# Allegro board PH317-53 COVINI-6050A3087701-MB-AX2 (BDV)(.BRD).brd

Outline 318.81 x 181 mm; copper layers: TOP, L2, L3, L4, L5, L6, L7, L8, L9, L10, L11, BOTTOM. Coordinates in mm from the lower left corner of the outline.

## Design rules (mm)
net group 1V8_MAIN_R_EN: nets 1V8_MAIN_R_EN GPIO4_1V8_MAIN_EN
net group 1V8S_DGPU_PG: nets 1V8_AON_PG 1V8S_DGPU_PG
net group ADC_MUX_R_SEL: nets ADC_MUX_R_SEL GPIO28_ADC_MUX_SEL
net group ALL_POWER_GOOD: nets ALL_POWER_GOOD DGPU_PWROK
net group ALL_PWGD_IN: nets ALL_PWGD_IN EN_PVCORE
net group ALL_PWGD_INTO_EC: nets ALL_PWGD_INTO_EC VCCIO_PG
net group AUD_CPU_SCLK: nets AUD_CPU_SCLK AUD_CPU_SCLK_R
net group AUD_CPU_SDI: nets AUD_CPU_SDI AUD_PCH_SDO
net group AUD_CPU_SDOP: nets AUD_CPU_SDOP AUD_PCH_SDI
net group BATT_CLK: nets BATT_CLK EC_SMB1_CLK
net group CHARGE_USBPWR_EN: nets CHARGE_USBPWR_EN USB_PWR_EN
net group CLINKCLK: nets CL_CLK1 CLINKCLK
net group CLINKDAT: nets CL_DATA1 CLINKDAT
net group CLINKRST#: nets CL_RST#1 CLINKRST#
net group CLK_CPU_D: nets CLK_CPU_DN CLK_CPU_DP
net group CLK_CPU_PCIBCLK_D: nets CLK_CPU_PCIBCLK_DN CLK_CPU_PCIBCLK_DP
net group CLK_CPUNSSC_D: nets CLK_CPUNSSC_DN CLK_CPUNSSC_DP
net group CLK_LAN_D: nets CLK_LAN_DN CLK_LAN_DP
net group CLK_PCIE_DGPU_100MHZ_: nets CLK_PCIE_DGPU_100MHZ_N CLK_PCIE_DGPU_100MHZ_P
net group CLK_PCIE_SSD1_D: nets CLK_PCIE_SSD1_DN CLK_PCIE_SSD1_DP
net group CLK_PCIE_SSD2_D: nets CLK_PCIE_SSD2_DN CLK_PCIE_SSD2_DP
net group CLK_WLAN_D: nets CLK_WLAN_DN CLK_WLAN_DP
net group CLKIN_XTAL: nets CLKIN_XTAL WLAN_CLK
net group CNV_BRI_DT: nets CNV_BRI_DT CNV_BRI_DT_R
net group CNV_BRI_RSP: nets CNV_BRI_RSP CNV_BRI_RSP_R
net group CNV_PA_BLANKING: nets CNV_PA_BLANKING CNV_PA_BLANKING_R
net group CNV_RF_RESET#_R: nets CNV_RF_RESET# CNV_RF_RESET#_R
net group CNV_RGI_DT: nets CNV_RGI_DT CNV_RGI_DT_R
net group CNV_RGI_RSP: nets CNV_RGI_RSP CNV_RGI_RSP_R
net group CNV_UART_RXD: nets CNV_UART_RXD CNV_UART_RXD_R
net group CNV_UART_TXD: nets CNV_UART_TXD CNV_UART_TXD_R
net group CPU2PCH_TRIGGER: nets CPU2PCH_TRIGGER CPU_TRIGOUT
net group DB_CLK_LAN_D: nets DB_CLK_LAN_DN DB_CLK_LAN_DP
net group DB_LAN_CLKREQ13#: nets DB_CLKREQ13_LAN# DB_LAN_CLKREQ13#
net group DB_PCIE_LAN_RX13: nets DB_PCIE_LAN_RX13N DB_PCIE_LAN_RX13P
net group DB_SPK_OUT_R_L_N: nets DB_SPK_OUT_R_L_N DB_SPK_OUT_R_L_P
net group DB_SPK_OUT_R_R_N: nets DB_SPK_OUT_R_R_N DB_SPK_OUT_R_R_P
net group DB_WOL_PWEN: nets DB_WOL_PWEN Q4021
net group DDR4_DRAMRST#_CPU: nets DDR4_DRAMRST#_CPU UNNAMED_284_CSC0402_I129_A
net group DDR_CA_CPU_VREF_RC: nets DDR_CA_CPU_VREF_A DDR_CA_CPU_VREF_RC
net group DDR_DQ_CPU_VREF_RC: nets DDR_DQ_CPU_VREF_B DDR_DQ_CPU_VREF_RC
net group DDR_PG_CTRL: nets DDR_PG_CTRL DDR_PG_CTRL_R
net group DDR_VTT_PG_CTRL: nets DDR_VTT_PG_CTRL EN_VTT
net group DGPU_ROM_CS#: nets DGPU_ROM_CS# VBIOS_CS#
net group DGPU_ROM_SCLK: nets DGPU_ROM_SCLK VBIOS_SCLK
net group DGPU_ROM_SI: nets DGPU_ROM_SI VBIOS_SI
net group DGPU_XTAL_OUT_DP: nets DGPU_XTAL_IN DGPU_XTAL_OUT
net group DMI_RX0_D: nets DMI_RX0_DN DMI_RX0_DP
net group DMI_RX1_D: nets DMI_RX1_DN DMI_RX1_DP
net group DMI_RX2_D: nets DMI_RX2_DN DMI_RX2_DP
net group DMI_RX3_D: nets DMI_RX3_DN DMI_RX3_DP
net group DMI_TX0_D: nets DMI_TX0_DN DMI_TX0_DP
net group DMI_TX1_D: nets DMI_TX1_DN DMI_TX1_DP
net group DMI_TX2_D: nets DMI_TX2_DN DMI_TX2_DP
net group DMI_TX3_D: nets DMI_TX3_DN DMI_TX3_DP
net group DMIC_DATA: nets DMIC__R_DATA DMIC_DATA
net group DP_CABLE_DET: nets DP_CABLE_DET DP_CABLE_R_DET
net group DP_IFPB_AUX: nets DP_IFPB_AUX DP_IFPB_AUX#
net group EC_CTL1: nets CTL1 EC_CTL1
net group EC_CTL2: nets CTL2 EC_CTL2
net group EC_CTL3: nets CTL3 EC_CTL3
net group EC_SMB1_DATA: nets EC_SMB1_DATA UNNAMED_131_CN082G_I95_3
net group EDP_PWM: nets EDP_PWM INV_PWM_PCH
net group EN_1V8: nets EN_1V8 UNNAMED_266_RSC0402_I167_A
net group EVENT_PCH#: nets EVENT_PCH# GPU_EVENT_PCH#
net group FBA_CLK0: nets FBA_CLK0 FBA_CLK0#
net group FBA_CLK1: nets FBA_CLK1 FBA_CLK1#
net group FBA_WCK01: nets FBA_WCK01 FBA_WCK01#
net group FBA_WCK23: nets FBA_WCK23 FBA_WCK23#
net group FBA_WCK45: nets FBA_WCK45 FBA_WCK45#
net group FBA_WCK67: nets FBA_WCK67 FBA_WCK67#
net group FBA_WCKB01: nets FBA_WCKB01 FBA_WCKB01#
net group FBA_WCKB23: nets FBA_WCKB23 FBA_WCKB23#
net group FBA_WCKB45: nets FBA_WCKB45 FBA_WCKB45#
net group FBA_WCKB67: nets FBA_WCKB67 FBA_WCKB67#
net group FBB_CLK0: nets FBB_CLK0 FBB_CLK0#
net group FBB_CLK1: nets FBB_CLK1 FBB_CLK1#
net group FBB_WCK01: nets FBB_WCK01 FBB_WCK01#
net group FBB_WCK23: nets FBB_WCK23 FBB_WCK23#
net group FBB_WCK45: nets FBB_WCK45 FBB_WCK45#
net group FBB_WCK67: nets FBB_WCK67 FBB_WCK67#
net group FBB_WCKB01: nets FBB_WCKB01 FBB_WCKB01#
net group FBB_WCKB23: nets FBB_WCKB23 FBB_WCKB23#
net group FBB_WCKB45: nets FBB_WCKB45 FBB_WCKB45#
net group FBB_WCKB67: nets FBB_WCKB67 FBB_WCKB67#
net group FBC_CLK0: nets FBC_CLK0 FBC_CLK0#
net group FBC_CLK1: nets FBC_CLK1 FBC_CLK1#
net group FBC_WCK01: nets FBC_WCK01 FBC_WCK01#
net group FBC_WCK23: nets FBC_WCK23 FBC_WCK23#
net group FBC_WCK45: nets FBC_WCK45 FBC_WCK45#
net group FBC_WCK67: nets FBC_WCK67 FBC_WCK67#
net group FBC_WCKB01: nets FBC_WCKB01 FBC_WCKB01#
net group FBC_WCKB23: nets FBC_WCKB23 FBC_WCKB23#
net group FBC_WCKB45: nets FBC_WCKB45 FBC_WCKB45#
net group FBC_WCKB67: nets FBC_WCKB67 FBC_WCKB67#
net group FBD_CLK0: nets FBD_CLK0 FBD_CLK0#
net group FBD_CLK1: nets FBD_CLK1 FBD_CLK1#
net group FBD_WCK01: nets FBD_WCK01 FBD_WCK01#
net group FBD_WCK23: nets FBD_WCK23 FBD_WCK23#
net group FBD_WCK45: nets FBD_WCK45 FBD_WCK45#
net group FBD_WCK67: nets FBD_WCK67 FBD_WCK67#
net group FBD_WCKB01: nets FBD_WCKB01 FBD_WCKB01#
net group FBD_WCKB23: nets FBD_WCKB23 FBD_WCKB23#
net group FBD_WCKB45: nets FBD_WCKB45 FBD_WCKB45#
net group FBD_WCKB67: nets FBD_WCKB67 FBD_WCKB67#
net group GC6_FB_EN_PCH: nets GC6_FB_EN_PCH GC6_FB_EN_PCH1
net group GPU_GND_SENSE: nets GPU_GND_SENSE NVVDD_GND_SENSE
net group GPU_HDMI_SCL: nets GPU_HDMI_SCL HDMI_GPU_SCL
net group GPU_HDMI_SDA: nets GPU_HDMI_SDA HDMI_GPU_SDA
net group GPU_NVVDD_SENSE: nets GPU_NVVDD_SENSE NVVDD_VCC_SENSE
net group GPU_OVERT_NVVDD#: nets 1V8_MAIN_EN_LEVEL GPU_OVERT_NVVDD#
net group GPU_PG: nets GPU_PG NVVDD_PG
net group GPU_THM_CLK: nets EC_SMBCLK0 GPU_THM_CLK
net group GPU_THM_DAT: nets EC_SMBDATA0 GPU_THM_DAT
net group H_PM_DOWN: nets H_PM_DOWN H_PM_DOWN_R
net group H_PM_SYNC: nets H_PM_SYNC H_PM_SYNC_R
net group H_PRDY#: nets H_PRDY# PCH_PRDY#
net group H_PREQ#: nets H_PREQ# PCH_PREQ#
net group H_TCK: nets H_TCK PCH_JTAGX
net group H_TDI: nets H_TDI PCH_TDI
net group H_TDO: nets H_TDO PCH_TDO
net group H_THERM#: nets H_THERM# THERMTRIP#
net group H_THERMDA: nets H_THERMDA H_THERMDC
net group H_TMS: nets H_TMS PCH_TMS
net group H_TRST#: nets H_TRST# PCH_TRST#
net group HDA_R_SDIN0: nets HDA_R_SDIN0 HDA_SDIN0
net group HDA_RST#: nets HDA_R_RST# HDA_RST#
net group HDA_SYNC: nets HDA_R_SYNC HDA_SYNC
net group HDMI_CN_DDCCLK: nets HDMI_CN_DDCCLK UNNAMED_171_NMOS2D2SDIODE_I12_2
net group HDMI_CN_DDCDATA: nets HDMI_CN_DDCDATA UNNAMED_171_NMOS2D2SDIODE_I12_4
net group HDMI_MPC_SCL: nets HDMI_MPC_SCL SMB0_CLK_D
net group HDMI_MPC_SDA: nets HDMI_MPC_SDA SMB0_DATA_D
net group HDMI_OUT_R_HPD: nets HDMI_CN_HPD HDMI_OUT_R_HPD
net group HDMI_RET_HPD: nets HDMI_NV_Q_HPD HDMI_RET_HPD
net group HPS: nets HPS UNNAMED_289_ALC255CG_I118_HP
net group I2CC_SCL_G: nets I2CC_SCL_G I2CC_SCL_R_G
net group I2CC_SDA_G: nets I2CC_SDA_G I2CC_SDA_R_G
net group I2CS_SCL_G: nets I2CS_SCL_G I2CS_SCL_R_G
net group I2CS_SDA_G: nets I2CS_SDA_G I2CS_SDA_R_G
net group I_ADP_R: nets HW_I_ADC I_ADP_R
net group IDCHG: nets IDCHG UNNAMED_264_IT8987ECX_I608_ADC1
net group IFPCD_PLLVDD: nets IFPCD_PLLVDD IFPE_PLLVDD
net group IRMT_HOLD_RST#: nets IRMT_HOLD_RST# PCH_HOLD_RST#
net group LAN_MDI3: nets LAN_MDI3N LAN_MDI3P
net group LAN_TRD0_CN_D: nets LAN_TRD0_CN_DN LAN_TRD0_CN_DP
net group LAN_TRD1_CN_D: nets LAN_TRD1_CN_DN LAN_TRD1_CN_DP
net group LAN_TRD2_CN_D: nets LAN_TRD2_CN_DN LAN_TRD2_CN_DP
net group LAN_TRD3_CN_D: nets LAN_TRD3_CN_DN LAN_TRD3_CN_DP
net group LCM_VDDEN: nets LCM_VDDEN UNNAMED_166_CSC0402_I36_A
net group LID_SW#_R: nets LID_SW# LID_SW#_R
net group LOW_PWR_VTG_SHIFT: nets LOW_PWR_VTG_SHIFT VID0_VCCIO
net group LOW_PWR_VTG_SHIFT_N: nets LOW_PWR_VTG_SHIFT_N VID1_VCCIO
net group LPC_AD<0>: nets LPC_AD<0> LPC_ESPI_IO0
net group LPC_AD<1>: nets LPC_AD<1> LPC_ESPI_IO1
net group LPC_AD<2>: nets LPC_AD<2> LPC_ESPI_IO2
net group LPC_AD<3>: nets LPC_AD<3> LPC_ESPI_IO3
net group M2_SSD1_DET#: nets M2_SSD1_DET# UNNAMED_160_NMOS_I89_G
net group M_A_DQS0_D: nets M_A_DQS0_DN M_A_DQS0_DP
net group M_A_DQS1_D: nets M_A_DQS1_DN M_A_DQS1_DP
net group M_A_DQS2_D: nets M_A_DQS2_DN M_A_DQS2_DP
net group M_A_DQS3_D: nets M_A_DQS3_DN M_A_DQS3_DP
net group M_A_DQS4_D: nets M_A_DQS4_DN M_A_DQS4_DP
net group M_A_DQS5_D: nets M_A_DQS5_DN M_A_DQS5_DP
net group M_A_DQS6_D: nets M_A_DQS6_DN M_A_DQS6_DP
net group M_A_DQS7_D: nets M_A_DQS7_DN M_A_DQS7_DP
net group M_B_DQS0_D: nets M_B_DQS0_DN M_B_DQS0_DP
net group M_B_DQS1_D: nets M_B_DQS1_DN M_B_DQS1_DP
net group M_B_DQS2_D: nets M_B_DQS2_DN M_B_DQS2_DP
net group M_B_DQS3_D: nets M_B_DQS3_DN M_B_DQS3_DP
net group M_B_DQS4_D: nets M_B_DQS4_DN M_B_DQS4_DP
net group M_B_DQS5_D: nets M_B_DQS5_DN M_B_DQS5_DP
net group M_B_DQS6_D: nets M_B_DQS6_DN M_B_DQS6_DP
net group M_B_DQS7_D: nets M_B_DQS7_DN M_B_DQS7_DP
net group M_CLK_DDR0_D: nets M_CLK_DDR0_DN M_CLK_DDR0_DP
net group M_CLK_DDR1_D: nets M_CLK_DDR1_DN M_CLK_DDR1_DP
net group M_CLK_DDR2_D: nets M_CLK_DDR2_DN M_CLK_DDR2_DP
net group M_CLK_DDR3_D: nets M_CLK_DDR3_DN M_CLK_DDR3_DP
net group MB_SHUTDOWN#: nets DGPU_PWRLEVEL MB_SHUTDOWN#
net group MODEM_CLKREQ_R: nets CNV_CLKREQ MODEM_CLKREQ_R
net group OVRM_EN_EC: nets OVRM_EN OVRM_EN_EC
net group PCH2CPU_TRIGGER: nets PCH2CPU_TRIGGER PCH_TRIGOUTGGER
net group PCH_I2C1_CLK: nets PCH_I2C1_CLK TP_I2C_CLK
net group PCH_I2C1_DATA: nets PCH_I2C1_DATA TP_I2C_DAT
net group PCH_SPI_SO2: nets PCH_SPI_SO2 UNNAMED_281_J44894_I301_SPI0IO2
net group PCH_SPI_SO3: nets PCH_SPI_SO3 UNNAMED_281_J44894_I301_SPI0IO3
net group PCH_THERMTRIP#: nets PCH_THERMTRIP# PCH_THERMTRIP#_R
net group PCH_VCCPRIM_1P8: nets PCH_VCCPRIM_1P8 PCH_VCCPRIM_1P8_R
net group PCIE_RCOMPN: nets PCIE_RCOMPN PCIE_RCOMPP
net group PCIE_SSD_RX9: nets PCIE_SSD_RX9N PCIE_SSD_RX9P
net group PCIE_SSD_RX10: nets PCIE_SSD_RX10N PCIE_SSD_RX10P
net group PCIE_SSD_RX11: nets PCIE_SSD_RX11N PCIE_SSD_RX11P
net group PCIE_SSD_RX12: nets PCIE_SSD_RX12N PCIE_SSD_RX12P
net group PCIE_SSD_RX21: nets PCIE_SSD_RX21N PCIE_SSD_RX21P
net group PCIE_SSD_RX22: nets PCIE_SSD_RX22N PCIE_SSD_RX22P
net group PCIE_SSD_RX23: nets PCIE_SSD_RX23N PCIE_SSD_RX23P
net group PCIE_SSD_RX24: nets PCIE_SSD_RX24N PCIE_SSD_RX24P
net group PCIE_WLAN_RX14: nets PCIE_WLAN_RX14N PCIE_WLAN_RX14P
net group PFM_PF_BSOK_RC: nets PFM_PF_BSOK_RC PFM_PF_R_BSOK
net group PVCORE_PG: nets PCH_PWROK PVCORE_PG
net group Q4001: nets Q4001 Q4023
net group REP_LAN_TX13: nets REP_LAN_TX13N REP_LAN_TX13P
net group SB_PWRBTN#_EC: nets SB_PWRBTN# SB_PWRBTN#_EC
net group SBPWR_EN_EC: nets SBPWR_EN_EC USBPWR_EN
net group SSD1_DEVSLP: nets DEVSLP_SSD1 SSD1_DEVSLP
net group SSD_CLKREQ2#: nets CLKREQ_SSD1# SSD_CLKREQ2#
net group SSD_CLKREQ3#: nets CLKREQ_SSD2# SSD_CLKREQ3#
net group THERM_SCI#: nets THERM_SCI# UNNAMED_262_RSC0402_I121_B
net group TPM_SPI_CS2#: nets PCH_SPI_CS2# TPM_SPI_CS2#
net group UNNAMED_131_CSC0603_I65_A: nets UNNAMED_131_CSC0603_I65_A UNNAMED_131_NMOSDUALC_I67_D1
net group UNNAMED_151_CSC0402_I5_A: nets UNNAMED_151_CSC0402_I5_A UNNAMED_151_NMOSC_I3_D
net group UNNAMED_153_1222UYOSUBCS530A4_1: nets UNNAMED_153_1222UYOSUBCS530A4_1 UNNAMED_153_NMOSDUALC_I22_D2
net group UNNAMED_153_1222UYOSUBCS530A4TR: nets UNNAMED_153_1222UYOSUBCS530A4TR UNNAMED_153_NMOSDUALC_I22_D1
net group UNNAMED_153_LEDSINGLE_I35_A1: nets UNNAMED_153_LEDSINGLE_I35_A1 UNNAMED_153_NMOSC_I26_D
net group UNNAMED_263_CSC0402_I83_A: nets UNNAMED_263_CSC0402_I83_A UNNAMED_263_NMOSC_I75_D
net group UNNAMED_285_J44894_I143_GPPA10: nets UNNAMED_285_J44894_I143_GPPA10 UNNAMED_285_RSC0402_I265_B
net group UNNAMED_289_ALC255CG_I118_CBN: nets UNNAMED_289_ALC255CG_I118_CBN UNNAMED_289_ALC255CG_I118_CBP
net group UNNAMED_314_CSC0402_I81_A: nets UNNAMED_314_CSC0402_I81_A UNNAMED_314_MP2886AGUZ_I21_VFB
net group USB2_REAR_3: nets USB2_REAR_3N USB2_REAR_3P
net group USB3_RX4: nets USB3_RX4N USB3_RX4P
net group USB3_RX5: nets USB3_RX5N USB3_RX5P
net group USB3_TX4: nets USB3_TX4N USB3_TX4P
net group USB3_TX5: nets USB3_TX5N USB3_TX5P
net group USB_P4_D: nets USB_P4_DN USB_P4_DP
net group USB_P5_D: nets USB_P5_DN USB_P5_DP
net group VCCGT_SENSE: nets VGT_VCCSENSE VGT_VSSSENSE
net group VCCIO_VSSSENSE: nets UNNAMED_139_CSC0402_I29_A VCCIO_VSSSENSE
net group VCCSA_SENSE: nets VCCSA_VCCSENSE VCCSA_VSSSENSE
net group VCCST_PWRGD: nets VCCST_PWRGD VCCST_PWRGD_CPU
net group VCORE_SENSE: nets VCCSENSE VSSSENSE
net group VR_SVID_ALERT#: nets VIDALERT# VR_SVID_ALERT#
net group VRACPU_SVID_CLK: nets VR_SVID_CLK VRACPU_SVID_CLK
net group VRACPU_SVID_DATA: nets VR_SVID_DATA VRACPU_SVID_DATA
net group VRB1V8S_BST: nets VRB1V8S_BST VRB1V8S_BST1
net group VSSMPHY_SENSE: nets VSSMPHY_SENSE VSSMPHY_SENSE_L
net group W4_S8: nets FAN1_PWM FAN2_PWM
net group WLAN_CLKREQ14#: nets CLKREQ14_WLAN# WLAN_CLKREQ14#
net group XTAL: nets DGPU_XTAL_OUTBUFF DGPU_XTAL_SSIN
net group 1V8_MAIN_EN_AND_LEVEL: nets 1V8_MAIN_EN_AND_LEVEL DGPU_PWR_EN DGPU_PWR_R_EN DIS_NVVDD EN_NVVDD EN_PEXVDD GPIO20_OR_FGC6 GPU_EN UNNAMED_169_NCT3521U_I119_3 UNNAMED_409_74LVC1G32_I108_1 UNNAMED_409_ANDGATE_I103_4
net group 19V_CURRENT_MONITOR_N: nets 19V_CURRENT_MONITOR_N 19V_CURRENT_MONITOR_P UNNAMED_402_CSC0402_I282_B UNNAMED_402_NCP45491XMNTWG_I2_4 UNNAMED_402_NCP45491XMNTWG_I2_6
net group ACDRV: nets UNNAMED_131_NMOSDUALC_I67_D2 UNNAMED_131_NMOSDUALC_I84_G2 VADPBL
net group ALWAYS_PW_EN: nets ALWAYS_PW_EN EN_3A5A EN_3V EN_5V EN_5V0 P5VDS_EN UNNAMED_132_RSC0402_I42_B UNNAMED_133_RSC0402_I17_B UNNAMED_134_CSC0402_I21_A UNNAMED_266_CSC0402_I474_A UNNAMED_266_NMOSC_I493_D
net group ASY: nets CATERR_N
net group AUDIO-B: nets DB_HP_R_L DB_HP_R_R RING2 SLEEVE
net group AVDDL: nets AVDDL AVDDVCO DVDDL
net group BATPRES#: nets BATPRES# BATT_IN# TS
net group BUF_PLT_RST#: nets BUF_PLT_RST# PCH_PLTRST#_BUF UNNAMED_264_IT8987ECX_I608_LPCR
net group CFG1_15: nets CFG<0> CFG<1> CFG<2> CFG<3> CFG<4> CFG<5> CFG<6> CFG<7> CFG<8> CFG<9> CFG<10> CFG<11> CFG<12> CFG<13> CFG<14> CFG<15>
net group CFG16_19: nets CFG<16> CFG<17> CFG<18> CFG<19>
net group CLK_LPC_EC: nets CLK_LPC_DEBUG_R CLK_LPC_EC LPC_ESPI_CLK UNNAMED_264_CSC0402_I634_A
net group CN_MIC: nets CN_MIC DB_MIC2_REF DB_RING2 DB_SLEEVE RING2_CONN
net group CORE_PWEN: nets CORE_PWEN CORE_PWEN_RC EN_VCCIO UNNAMED_265_APL3523A_I457_3 UNNAMED_265_APL3523A_I457_5 UNNAMED_265_APL3523A_I458_5 UNNAMED_315_NMOS_I101_G
net group CPU_C10_PWR_GATE#_R: nets CPU_C10_PWR_GATE#_R LP# UNNAMED_265_ANDGATE_I549_1
net group CPU_PROCHOT#: nets CPU_PROCHOT# CPU_PROCHOT#_R EC_CPU_PROCHOT# PROCHOT#
net group DB_PCIE_LAN_C_TX13N: nets UNNAMED_206_CSC0402_I359_A
net group DB_PCIE_LAN_C_TX13P: nets UNNAMED_206_CSC0402_I360_A
net group DIS_FBVDD: nets DIS_FBVDD EN_VRAM_DGPU FBVDD_EN_OR
net group DIS_PEXVDD: nets DIS_PEXVDD EN_1V0S_DGPU EN_PEXVDD_AND
net group DMIC_CLK: nets DMIC_CLK DMIC_CLK_R DMIC_R_CLK
net group DP_CLK: nets DPB_DDCCLK DPC_DDCCLK HDMI_DDCCLK HDMI_TXSCL
net group DP_CN_HPD: nets DP_CN_HPD DP_NA_HPD DP_NV_HPD DP_REP_HPD
net group DP_DATA: nets DPB_DDCDATA DPC_DDCDATA HDMI_TXSDA
net group EC_PECI: nets EC_PECI H_PECI PCH_PECI PCH_R_PECI
net group EC_PWRBTN#: nets EC_PWRBTN# UNNAMED_151_CN282G_I20_28 UNNAMED_264_IT8987ECX_I608_PWRS
net group EDP_BKLTEN: nets EDP_BKLTEN LCM_BKLTEN LID_SW_LCM#
net group ESPI_RST#: nets ESPI_RST# GPP_A7 KB_RST# SERIRQ SERIRQ_ESPI_RST# UNNAMED_285_RSC0402_I283_B
net group GND: nets AGND_AUDIO DGND_CHASSIS1 DGND_CHASSIS2 DGND_CHASSIS4 DGND_CHASSIS5 DGPU_FB_CAL_PU_GND DGPU_FB_CAL_TERM_GND GND_A GND_A1 GND_ALG GND_PB VRAM_DGPU_GND
net group GPU_DP_AUX: nets UNNAMED_398_CSC0402_I129_A
net group GPU_DP_AUX#: nets UNNAMED_398_CSC0402_I130_A
net group HDA_BCLK: nets HDA_BCLK HDA_R_BCLK HDA_R_BITCLK
net group HDA_SDO: nets HDA_SDO HDA_SDO_R ME_FLASH_EN
net group HDMI_ISP_SCL: nets HDMI_ISP_SCL HDMI_RET_SCL UNNAMED_171_NMOS2D2SDIODE_I12_3
net group HDMI_ISP_SDA: nets HDMI_ISP_SDA HDMI_RET_SDA UNNAMED_171_NMOS2D2SDIODE_I126_
net group HP_L: nets HP_L HP_R_L LINE1_L LINE1_REF_L
net group HP_R: nets HP_R HP_R_R LINE1_R LINE1_REF_R
net group I2C_RST#: nets I2C_RST# OVERT_RST# PEX_DGPU_RST#
net group LPC: nets ESPI_LPC#
net group M2_SSD1_SUSCLK: nets M2_SSD1_SUSCLK M2_SSD2_SUSCLK M2_WLAN_SUSCLK SUSCLK SUSCLK32_PCH
net group NVVDD_CURRENT_MONITOR_N: nets NVVDD_CURRENT_MONITOR_N NVVDD_CURRENT_MONITOR_P UNNAMED_402_CSC0402_I285_B UNNAMED_402_NCP45491XMNTWG_I2_1 UNNAMED_402_NCP45491XMNTWG_I2_5 UNNAMED_402_NCP45491XMNTWG_I2_7 UNNAMED_402_NCP45491XMNTWG_I267
net group NVVDD_PSI: nets GPIO6_NVVDD_PSI# NVVDD_PSI UNNAMED_314_MP2886AGUZ_I21_PSI
net group NVVDD_PWMID: nets GPIO0_GPU_VID NVVDD_PWMID UNNAMED_314_MP2886AGUZ_I21_PWMV
net group PCH_SPI_SO: nets PCH_SPI_SO SPI_EC_SO TPM_SPI_SO UNNAMED_281_J44894_I301_SPI0MIS
net group PCSPKR_EC_3: nets PCH_SPKR PCSPKR_EC_3 UNNAMED_289_ALC255CG_I118_PCBEE UNNAMED_289_CSC0402_I68_B
net group PEG_RCOMP: nets PEG_RCOMP
net group PFM_BG_REF_OUT: nets PFM_BG_REF_OUT PFM_BS_REF PFM_CM_REF_IN UNNAMED_402_NPND_I214_C
net group PWR: nets FBA1_VREFC FBA2_VREFC FBB1_VREFC FBB2_VREFC FBC1_VREFC FBC2_VREFC FBD1_VREFC FBD2_VREFC GPU_FB_VREF NV3V3_DPP_DIS P0V6S P0V6S_DIMM0_VREF_CA P0V6S_DIMM1_VREF_DQ P1V0S_DGPU P1V0S_HDMI P1V2 P1V05A P1V8_MAIN P1V8_MAIN_CT P1V8A P1V8A_1P P1V8S P1V8S_AON1 P1V8S_AON2 P1V8S_AUDIO P1V8S_MAIN1 P1V35S_FBVDDQ P2V5 P3V3_NV_SEQ P3V3_RTC P3V3A P3V3A_KBLED P3V3A_LAN P3V3A_PB P3V3A_WLAN P3V3AL P3V3AL_EC_AVCC P3V3AL_EC_FSPI P3V3AL_EC_VSTBY_PLL P3V3AL_RTC_BAT P3V3AL_RTC_BAT_BOT P3V3AL_RTC_BAT_R P3V3AL_SM P3V3DS P3V3DS_PB P3V3S P3V3S_DP P3V3S_DPP P3V3S_EC_VCC P3V3S_HDMI P3V3S_LCDVDD2 P3V3S_SENSOR P3V3S_TP P5V0 P5V0A_PB P5V0A_USB1 P5V0DS P5V0S P5V0S_AUDIO_AVDD P5V0S_FAN1 P5V0S_FAN2 P5V0S_HDMI P5V0S_KBLED P5V0S_PVDD PUSB3_PWR2 PVADPTR PVBAT PVBAT_CPU PVBAT_GT PVBAT_SA PVCCGT PVCCIO PVCCSA PVCCST PVCCSTG PVCORE PVCORE_DGPU PVPACK VCCPLL_OC VCCSFR VRAM_DGPU_VREF
net group REPEATER_HDMI_CLKN: nets UNNAMED_171_AZ104504FR7G_I86_5
net group REPEATER_HDMI_CLKP: nets UNNAMED_171_AZ104504FR7G_I86_4
net group REPEATER_HDMI_D0N: nets REPEATER_HDMI_D0N
net group REPEATER_HDMI_D0P: nets REPEATER_HDMI_D0P
net group REPEATER_HDMI_D1N: nets REPEATER_HDMI_D1N
net group REPEATER_HDMI_D1P: nets REPEATER_HDMI_D1P
net group REPEATER_HDMI_D2N: nets REPEATER_HDMI_D2N
net group REPEATER_HDMI_D2P: nets REPEATER_HDMI_D2P
net group RESUME_PWEN: nets 2V5_PG EN_2V5 EN_VDDQ PVCCSTG_EN RESUME_PWEN UNNAMED_265_ANDGATE_I549_4 UNNAMED_266_RSC0402_I529_A VCCPLL_OC_EN
net group RSMRST_EC: nets 3V3DS_PG RSMRST# RSMRST_EC UNNAMED_264_IT8987ECX_I608_LPCP UNNAMED_266_RSC0402_I374_A
net group SCAN_IN: nets SCAN_IN<0> SCAN_IN<1> SCAN_IN<2> SCAN_IN<3> SCAN_IN<4> SCAN_IN<5> SCAN_IN<6> SCAN_IN<7>
net group SCAN_OUT: nets SCAN_OUT<0> SCAN_OUT<1> SCAN_OUT<2> SCAN_OUT<3> SCAN_OUT<4> SCAN_OUT<5> SCAN_OUT<6> SCAN_OUT<7> SCAN_OUT<8> SCAN_OUT<9> SCAN_OUT<10> SCAN_OUT<11> SCAN_OUT<12> SCAN_OUT<13> SCAN_OUT<14> SCAN_OUT<15> SCAN_OUT<16> SCAN_OUT<17>
net group SCLK: nets I2C_CLK_LED I2CB_SCL_G I2CC_SCL PCH_3A_SMCLK PCH_3S_SMCLK PCH_I2C_CLK PCH_TCK SMB0_CLK TP_CLK WLAN_I2C_CLK XCLK_BIASREF
net group SCLK_DATA: nets DGPU_ROM_SO HDMI_DDCDATA I2C_DATA_LED I2CB_SDA_G I2CC_SDA PCH_3A_SMDATA PCH_3S_SMDATA PCH_I2C_DATA SMB0_DATA SMBALERT# TP_DATA WLAN_I2C_DAT
net group SDDR_A_ALERT: nets M_A_ALERT#
net group SDDR_A_CMD: nets M_A_A_0 M_A_A_1 M_A_A_2 M_A_A_3 M_A_A_4 M_A_A_5 M_A_A_6 M_A_A_7 M_A_A_8 M_A_A_9 M_A_A_10 M_A_A_11 M_A_A_12 M_A_A_13 M_A_ACT# M_A_BG0 M_A_BG1 M_A_BS0 M_A_BS1 M_A_CAS# M_A_PARITY M_A_RAS# M_A_WE# M_CKE0 M_CKE1 M_CS#0 M_CS#1 M_ODT0 M_ODT1
net group SDDR_A_DQ_BYTE0: nets M_A_DQ<0> M_A_DQ<1> M_A_DQ<2> M_A_DQ<3> M_A_DQ<4> M_A_DQ<5> M_A_DQ<6> M_A_DQ<7>
net group SDDR_A_DQ_BYTE1: nets M_A_DQ<8> M_A_DQ<9> M_A_DQ<10> M_A_DQ<11> M_A_DQ<12> M_A_DQ<13> M_A_DQ<14> M_A_DQ<15>
net group SDDR_A_DQ_BYTE2: nets M_A_DQ<16> M_A_DQ<17> M_A_DQ<18> M_A_DQ<19> M_A_DQ<20> M_A_DQ<21> M_A_DQ<22> M_A_DQ<23>
net group SDDR_A_DQ_BYTE3: nets M_A_DQ<24> M_A_DQ<25> M_A_DQ<26> M_A_DQ<27> M_A_DQ<28> M_A_DQ<29> M_A_DQ<30> M_A_DQ<31>
net group SDDR_A_DQ_BYTE4: nets M_A_DQ<32> M_A_DQ<33> M_A_DQ<34> M_A_DQ<35> M_A_DQ<36> M_A_DQ<37> M_A_DQ<38> M_A_DQ<39>
net group SDDR_A_DQ_BYTE5: nets M_A_DQ<40> M_A_DQ<41> M_A_DQ<42> M_A_DQ<43> M_A_DQ<44> M_A_DQ<45> M_A_DQ<46> M_A_DQ<47>
net group SDDR_A_DQ_BYTE6: nets M_A_DQ<48> M_A_DQ<49> M_A_DQ<50> M_A_DQ<51> M_A_DQ<52> M_A_DQ<53> M_A_DQ<54> M_A_DQ<55>
net group SDDR_A_DQ_BYTE7: nets M_A_DQ<56> M_A_DQ<57> M_A_DQ<58> M_A_DQ<59> M_A_DQ<60> M_A_DQ<61> M_A_DQ<62> M_A_DQ<63>
net group SDDR_B_ALERT: nets M_B_ALERT#
net group SDDR_B_CMD: nets M_B_A_0 M_B_A_1 M_B_A_2 M_B_A_3 M_B_A_4 M_B_A_5 M_B_A_6 M_B_A_7 M_B_A_8 M_B_A_9 M_B_A_10 M_B_A_11 M_B_A_12 M_B_A_13 M_B_ACT# M_B_BG0 M_B_BG1 M_B_BS0 M_B_BS1 M_B_CAS# M_B_PARITY M_B_RAS# M_B_WE# M_CKE2 M_CKE3 M_CS#2 M_CS#3 M_ODT2 M_ODT3
net group SDDR_B_DQ_BYTE0: nets M_B_DQ<0> M_B_DQ<1> M_B_DQ<2> M_B_DQ<3> M_B_DQ<4> M_B_DQ<5> M_B_DQ<6> M_B_DQ<7>
net group SDDR_B_DQ_BYTE1: nets M_B_DQ<8> M_B_DQ<9> M_B_DQ<10> M_B_DQ<11> M_B_DQ<12> M_B_DQ<13> M_B_DQ<14> M_B_DQ<15>
net group SDDR_B_DQ_BYTE2: nets M_B_DQ<16> M_B_DQ<17> M_B_DQ<18> M_B_DQ<19> M_B_DQ<20> M_B_DQ<21> M_B_DQ<22> M_B_DQ<23>
net group SDDR_B_DQ_BYTE3: nets M_B_DQ<24> M_B_DQ<25> M_B_DQ<26> M_B_DQ<27> M_B_DQ<28> M_B_DQ<29> M_B_DQ<30> M_B_DQ<31>
net group SDDR_B_DQ_BYTE4: nets M_B_DQ<32> M_B_DQ<33> M_B_DQ<34> M_B_DQ<35> M_B_DQ<36> M_B_DQ<37> M_B_DQ<38> M_B_DQ<39>
net group SDDR_B_DQ_BYTE5: nets M_B_DQ<40> M_B_DQ<41> M_B_DQ<42> M_B_DQ<43> M_B_DQ<44> M_B_DQ<45> M_B_DQ<46> M_B_DQ<47>
net group SDDR_B_DQ_BYTE6: nets M_B_DQ<48> M_B_DQ<49> M_B_DQ<50> M_B_DQ<51> M_B_DQ<52> M_B_DQ<53> M_B_DQ<54> M_B_DQ<55>
net group SDDR_B_DQ_BYTE7: nets M_B_DQ<56> M_B_DQ<57> M_B_DQ<58> M_B_DQ<59> M_B_DQ<60> M_B_DQ<61> M_B_DQ<62> M_B_DQ<63>
net group SDDR_RCOMP: nets DDR_RCOMP_0 DDR_RCOMP_1 DDR_RCOMP_2
net group SDDR_VREF: nets DDR_DQ_CPU_VREF_A
net group SPI_DATA: nets SPI0_CS1#
net group SPI_EC_CS0#: nets PCH_SPI_CS0# SPI_EC_CS0# UNNAMED_281_J44894_I301_SPI0CS0
net group SPI_EC_SI: nets PCH_SPI_SI SPI_EC_SI TPM_SPI_SI UNNAMED_281_J44894_I301_SPI0MOS
net group SVID_PECI_THERMTRIP: nets CPU_THERMTRIP#
net group TOUCHPAD_I2C_INT#: nets PCH_TP_I2C_INT# TOUCHPAD_I2C_INT# TP_I2C_INT# UNNAMED_152_RSC0402_I29_A UNNAMED_264_IT8987ECX_I608_ID5
net group TPM_SPI_CLK: nets PCH_SPI_CLK SPI_EC_CLK TPM_SPI_CLK UNNAMED_281_J44894_I301_SPI0CLK
net group UNNAMED_130_BQ24780S_I45_17: nets UNNAMED_130_BQ24780S_I45_17
net group UNNAMED_133_CSC0402_I21_A: nets UNNAMED_133_CSC0402_I21_A UNNAMED_133_CSC0402_I21_B UNNAMED_133_POWERPAD40610_I32_3 UNNAMED_133_RSCSHORT_I25_A
net group UNNAMED_166_NCT3521U_I118_4: nets UNNAMED_166_NCT3521U_I118_4
net group UNNAMED_259_CSC0402_I152_A: nets UNNAMED_259_CSC0402_I152_A UNNAMED_259_CSC1206_I129_A UNNAMED_259_NA0069RLF_I116_16 UNNAMED_259_NA0069RLF_I116_21 UNNAMED_259_NA0069RLF_I116_22 UNNAMED_259_NA0069RLF_I116_TXTC
net group VCCIO_SENSE: nets VCCIO_VCCSENSE
net group VCCMPHY_SENSE: nets DGPU_FBVDDQ_SENSE VCCMPHY_SENSE VCCMPHY_SENSE_L VRAM_DGPU_VCC_SENSE VRAM_DGPU_VSS_SENSE
net group VRA: nets PVBAT_VRAM_DGPU TYPEC_CC1 TYPEC_CC2 VRA1V05A_FB VRA1V05A_FF VRA1V05A_ILMT VRA1V05A_SNB VRA1V05A_VOUT VRA1V8A_FB VRA1V35_SNB VRA2V5_FB VRA3V3A_SNB VRA3V3A_VCC VRA3V3DS_VOUT VRA5V0_LDO VRA5V0_SNB VRA5V0A_FF VRA5V0A_FF_R VRA5V0A_LDO VRA5V0A_SNB VRA5V0A_VOUT VRA_SY8288_VCC VRACHG_ACDET VRACHG_ACDRV VRACHG_ACN VRACHG_ACP VRACHG_BATDRV VRACHG_BATDRV1 VRACHG_BST VRACHG_BST1 VRACHG_CMSRC VRACHG_ILIM VRACHG_MP1 VRACHG_REGN VRACHG_SNB VRACHG_SRN VRACHG_SRN1 VRACHG_SRP VRACHG_SRP1 VRACHG_VCC VRACPU_BST1 VRACPU_BST2 VRACPU_BST3 VRACPU_BST4 VRACPU_BST11 VRACPU_BST12 VRACPU_BST21 VRACPU_BST22 VRACPU_BST31 VRACPU_BST32 VRACPU_BST41 VRACPU_BST42 VRACPU_COMP VRACPU_COMP1 VRACPU_CSCOMP VRACPU_CSCOMP1 VRACPU_CSN1 VRACPU_CSN2 VRACPU_CSN3 VRACPU_CSN4 VRACPU_CSN11 VRACPU_CSN21 VRACPU_CSN31 VRACPU_CSN41 VRACPU_CSP1 VRACPU_CSP1_R VRACPU_CSP2 VRACPU_CSP2_R VRACPU_CSP3 VRACPU_CSP3_R VRACPU_CSP4 VRACPU_CSP4_R VRACPU_CSP11 VRACPU_CSP21 VRACPU_CSP31 VRACPU_CSP41 VRACPU_CSREF VRACPU_CSSUM VRACPU_DIFFOUT VRACPU_DRVON VRACPU_FB VRACPU_FB1 VRACPU_ILIM VRACPU_IMON VRACPU_PH1 VRACPU_PH2 VRACPU_PH3 VRACPU_PH4 VRACPU_PROCHOT# VRACPU_PSYS VRACPU_PWM1 VRACPU_PWM2 VRACPU_PWM3 VRACPU_PWM4 VRACPU_SNB1 VRACPU_SNB2 VRACPU_SNB3 VRACPU_SNB4 VRACPU_TSENSE VRACPU_TSENSE1 VRACPU_VCC VRACPU_VRMP VRACPU_VSN VRACPU_VSN1 VRACPU_VSP VRAGT_BST1 VRAGT_BST11 VRAGT_COMP VRAGT_COMP1 VRAGT_CSCOMP VRAGT_CSCOMP1 VRAGT_CSN1 VRAGT_CSN11 VRAGT_CSP1 VRAGT_CSP1_R VRAGT_CSP2_R VRAGT_CSP11 VRAGT_CSREF VRAGT_CSSUM VRAGT_DIFFOUT VRAGT_FB VRAGT_FB1 VRAGT_ILIM VRAGT_IMON VRAGT_PWM1 VRAGT_PWM2 VRAGT_SNB1 VRAGT_TSENSE VRAGT_TSENSE1 VRAGT_VSN VRAGT_VSN1 VRAGT_VSP VRAM_DGPU_BST1 VRAM_DGPU_BST2 VRAM_DGPU_EN VRAM_DGPU_HG1 VRAM_DGPU_HG2 VRAM_DGPU_LG1 VRAM_DGPU_LG2 VRAM_DGPU_PH1 VRAM_DGPU_PH2 VRAM_DGPU_PVCC VRASA_BST1 VRASA_BST11 VRASA_COMP VRASA_COMP1 VRASA_CSN1 VRASA_CSN11 VRASA_CSP1 VRASA_CSP1_R VRASA_CSP11 VRASA_ILIM VRASA_IMON VRASA_PWM1 VRASA_SNB1 VRASA_VSN VRASA_VSN1 VRASA_VSP VRASA_VSP1 VRAVCCIO_BST VRAVCCIO_BST1 VRAVCCIO_MODE VRAVCCIO_SNB VRAVDDQ_BST VRAVDDQ_BST1 VRAVDDQ_FB VRAVDDQ_MODE VRAVDDQ_OTW# VRAVDDQ_VOUT VRP3V3A_LDO
net group VRA1V8S_FB: nets VRA1V8S_FB VRA1V8S_FF VRA1V8S_VOUT
net group VRAM_A_CMD: nets FBA_CMD0 FBA_CMD1 FBA_CMD2_RST FBA_CMD3 FBA_CMD4 FBA_CMD5 FBA_CMD6 FBA_CMD7 FBA_CMD8 FBA_CMD9 FBA_CMD10_CKE FBA_CMD11 FBA_CMD12 FBA_CMD13 FBA_CMD14 FBA_CMD15 FBA_CMD16 FBA_CMD17 FBA_CMD18_RST FBA_CMD19 FBA_CMD20 FBA_CMD21 FBA_CMD22 FBA_CMD23 FBA_CMD24 FBA_CMD25 FBA_CMD26_CKE FBA_CMD27 FBA_CMD28 FBA_CMD29 FBA_CMD30 FBA_CMD31 FBA_CMD32 FBA_CMD33
net group VRAM_A_DBI: nets FBA_DBI0 FBA_DBI1 FBA_DBI2 FBA_DBI3 FBA_DBI4 FBA_DBI5 FBA_DBI6 FBA_DBI7
net group VRAM_A_DQ: nets FBA_D0 FBA_D1 FBA_D2 FBA_D3 FBA_D4 FBA_D5 FBA_D6 FBA_D7 FBA_D8 FBA_D9 FBA_D10 FBA_D11 FBA_D12 FBA_D13 FBA_D14 FBA_D15 FBA_D16 FBA_D17 FBA_D18 FBA_D19 FBA_D20 FBA_D21 FBA_D22 FBA_D23 FBA_D24 FBA_D25 FBA_D26 FBA_D27 FBA_D28 FBA_D29 FBA_D30 FBA_D31 FBA_D32 FBA_D33 FBA_D34 FBA_D35 FBA_D36 FBA_D37 FBA_D38 FBA_D39 FBA_D40 FBA_D41 FBA_D42 FBA_D43 FBA_D44 FBA_D45 FBA_D46 FBA_D47 FBA_D48 FBA_D49 FBA_D50 FBA_D51 FBA_D52 FBA_D53 FBA_D54 FBA_D55 FBA_D56 FBA_D57 FBA_D58 FBA_D59 FBA_D60 FBA_D61 FBA_D62 FBA_D63
net group VRAM_A_EDC: nets FBA_EDC0 FBA_EDC1 FBA_EDC2 FBA_EDC3 FBA_EDC4 FBA_EDC5 FBA_EDC6 FBA_EDC7
net group VRAM_B_CMD: nets FBB_CMD0 FBB_CMD1 FBB_CMD2_RST FBB_CMD3 FBB_CMD4 FBB_CMD5 FBB_CMD6 FBB_CMD7 FBB_CMD8 FBB_CMD9 FBB_CMD10_CKE FBB_CMD11 FBB_CMD12 FBB_CMD13 FBB_CMD14 FBB_CMD15 FBB_CMD16 FBB_CMD17 FBB_CMD18_RST FBB_CMD19 FBB_CMD20 FBB_CMD21 FBB_CMD22 FBB_CMD23 FBB_CMD24 FBB_CMD25 FBB_CMD26_CKE FBB_CMD27 FBB_CMD28 FBB_CMD29 FBB_CMD30 FBB_CMD31 FBB_CMD32 FBB_CMD33
net group VRAM_B_DBI: nets FBB_DBI0 FBB_DBI1 FBB_DBI2 FBB_DBI3 FBB_DBI4 FBB_DBI5 FBB_DBI6 FBB_DBI7
net group VRAM_B_DQ: nets FBB_D0 FBB_D1 FBB_D2 FBB_D3 FBB_D4 FBB_D5 FBB_D6 FBB_D7 FBB_D8 FBB_D9 FBB_D10 FBB_D11 FBB_D12 FBB_D13 FBB_D14 FBB_D15 FBB_D16 FBB_D17 FBB_D18 FBB_D19 FBB_D20 FBB_D21 FBB_D22 FBB_D23 FBB_D24 FBB_D25 FBB_D26 FBB_D27 FBB_D28 FBB_D29 FBB_D30 FBB_D31 FBB_D32 FBB_D33 FBB_D34 FBB_D35 FBB_D36 FBB_D37 FBB_D38 FBB_D39 FBB_D40 FBB_D41 FBB_D42 FBB_D43 FBB_D44 FBB_D45 FBB_D46 FBB_D47 FBB_D48 FBB_D49 FBB_D50 FBB_D51 FBB_D52 FBB_D53 FBB_D54 FBB_D55 FBB_D56 FBB_D57 FBB_D58 FBB_D59 FBB_D60 FBB_D61 FBB_D62 FBB_D63
net group VRAM_B_EDC: nets FBB_EDC0 FBB_EDC1 FBB_EDC2 FBB_EDC3 FBB_EDC4 FBB_EDC5 FBB_EDC6 FBB_EDC7
net group VRAM_C_CMD: nets FBC_CMD0 FBC_CMD1 FBC_CMD2_RST FBC_CMD3 FBC_CMD4 FBC_CMD5 FBC_CMD6 FBC_CMD7 FBC_CMD8 FBC_CMD9 FBC_CMD10_CKE FBC_CMD11 FBC_CMD12 FBC_CMD13 FBC_CMD14 FBC_CMD15 FBC_CMD16 FBC_CMD17 FBC_CMD18_RST FBC_CMD19 FBC_CMD20 FBC_CMD21 FBC_CMD22 FBC_CMD23 FBC_CMD24 FBC_CMD25 FBC_CMD26_CKE FBC_CMD27 FBC_CMD28 FBC_CMD29 FBC_CMD30 FBC_CMD31 FBC_CMD32 FBC_CMD33
net group VRAM_C_DBI: nets FBC_DBI0 FBC_DBI1 FBC_DBI2 FBC_DBI3 FBC_DBI4 FBC_DBI5 FBC_DBI6 FBC_DBI7
net group VRAM_C_DQ: nets FBC_D0 FBC_D1 FBC_D2 FBC_D3 FBC_D4 FBC_D5 FBC_D6 FBC_D7 FBC_D8 FBC_D9 FBC_D10 FBC_D11 FBC_D12 FBC_D13 FBC_D14 FBC_D15 FBC_D16 FBC_D17 FBC_D18 FBC_D19 FBC_D20 FBC_D21 FBC_D22 FBC_D23 FBC_D24 FBC_D25 FBC_D26 FBC_D27 FBC_D28 FBC_D29 FBC_D30 FBC_D31 FBC_D32 FBC_D33 FBC_D34 FBC_D35 FBC_D36 FBC_D37 FBC_D38 FBC_D39 FBC_D40 FBC_D41 FBC_D42 FBC_D43 FBC_D44 FBC_D45 FBC_D46 FBC_D47 FBC_D48 FBC_D49 FBC_D50 FBC_D51 FBC_D52 FBC_D53 FBC_D54 FBC_D55 FBC_D56 FBC_D57 FBC_D58 FBC_D59 FBC_D60 FBC_D61 FBC_D62 FBC_D63
net group VRAM_C_EDC: nets FBC_EDC0 FBC_EDC1 FBC_EDC2 FBC_EDC3 FBC_EDC4 FBC_EDC5 FBC_EDC6 FBC_EDC7
net group VRAM_D_CMD: nets FBD_CMD0 FBD_CMD1 FBD_CMD2_RST FBD_CMD3 FBD_CMD4 FBD_CMD5 FBD_CMD6 FBD_CMD7 FBD_CMD8 FBD_CMD9 FBD_CMD10_CKE FBD_CMD11 FBD_CMD12 FBD_CMD13 FBD_CMD14 FBD_CMD15 FBD_CMD16 FBD_CMD17 FBD_CMD18_RST FBD_CMD19 FBD_CMD20 FBD_CMD21 FBD_CMD22 FBD_CMD23 FBD_CMD24 FBD_CMD25 FBD_CMD26_CKE FBD_CMD27 FBD_CMD28 FBD_CMD29 FBD_CMD30 FBD_CMD31 FBD_CMD32 FBD_CMD33
net group VRAM_D_DBI: nets FBD_DBI0 FBD_DBI1 FBD_DBI2 FBD_DBI3 FBD_DBI4 FBD_DBI5 FBD_DBI6 FBD_DBI7
net group VRAM_D_DQ: nets FBD_D0 FBD_D1 FBD_D2 FBD_D3 FBD_D4 FBD_D5 FBD_D6 FBD_D7 FBD_D8 FBD_D9 FBD_D10 FBD_D11 FBD_D12 FBD_D13 FBD_D14 FBD_D15 FBD_D16 FBD_D17 FBD_D18 FBD_D19 FBD_D20 FBD_D21 FBD_D22 FBD_D23 FBD_D24 FBD_D25 FBD_D26 FBD_D27 FBD_D28 FBD_D29 FBD_D30 FBD_D31 FBD_D32 FBD_D33 FBD_D34 FBD_D35 FBD_D36 FBD_D37 FBD_D38 FBD_D39 FBD_D40 FBD_D41 FBD_D42 FBD_D43 FBD_D44 FBD_D45 FBD_D46 FBD_D47 FBD_D48 FBD_D49 FBD_D50 FBD_D51 FBD_D52 FBD_D53 FBD_D54 FBD_D55 FBD_D56 FBD_D57 FBD_D58 FBD_D59 FBD_D60 FBD_D61 FBD_D62 FBD_D63
net group VRAM_D_EDC: nets FBD_EDC0 FBD_EDC1 FBD_EDC2 FBD_EDC3 FBD_EDC4 FBD_EDC5 FBD_EDC6 FBD_EDC7
net group VRB: nets VRB1V05A_BST VRB1V05A_BST1 VRB3V3A_BST VRB3V3A_BST1 VRB5V0_BST VRB5V0_BST1 VRB5V0_VCC VRB5V0A_BST VRB5V0A_BST1 VRB5V0A_VCC VRB_VDD3 VRB_VDD5
net group VRP: nets VRAP1V0S_DGPU_FB VRP1V0S_DGPU_PH VRP1V2_PH VRP1V05A VRP1V05A_PH VRP1V05A_VIN VRP1V8 VRP1V8A VRP1V8A_PH VRP1V8A_VIN VRP1V8S_VIN VRP2V5 VRP2V5_PH VRP2V5_VIN VRP3V3A VRP3V3A_PH VRP3V3A_RTC VRP3V3A_VIN VRP5V0 VRP5V0_PH VRP5V0_VIN VRP5V0A VRP5V0A_PH VRP5V0A_VIN VRPCHG_HG VRPCHG_LG VRPCHG_PH VRPGPU_BST1 VRPGPU_BST2 VRPGPU_BST3 VRPGPU_BST4 VRPGPU_BST5 VRPGPU_BST6 VRPGPU_SW1 VRPGPU_SW2 VRPGPU_SW3 VRPGPU_SW4 VRPGPU_SW5 VRPGPU_SW6 VRPGT_HG1 VRPGT_LG1 VRPGT_PH1 VRPSA_HG1 VRPSA_LG1 VRPSA_PH1 VRPVBAT_DGPU VRPVBAT_NVVDD VRPVCCIO VRPVCCIO_PH VRPVCCIO_VIN VRPVDDQ VRPVDDQ_PH VRPVDDQ_VIN VRPVTT VRPVTT_REF
net group X401_3: nets X401_3 XTLI XTLO
net group XTAL24_IN: nets XTAL24_IN XTAL24_IN_R XTAL24_OUT XTAL24_OUT_R
net group XTAL_VCC: nets VCC_XTAL

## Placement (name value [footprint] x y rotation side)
C3  0.1uF_16V_2  [CSC_100X050X040_2]  232.33 37.19 180 bottom
C4  1uF_6.3V_2  [CSC_100X050X055_2]  249.5 59.69 90 top
C5  1uF_6.3V_2  [CSC_100X050X055_2]  251.48 58.02 270 top
C6  4.7uF_6.3V_3  [CSC_160X080X090_2]  264.77 65.18 0 bottom
C7  4.7uF_6.3V_3  [CSC_160X080X090_2]  252.57 56.9 90 top
C8  1uF_6.3V_2  [CSC_100X050X055_2]  250.29 55.17 180 top
C9  1uF_6.3V_2  [CSC_100X050X055_2]  252.75 55.2 0 top
C10  0.1uF_16V_2  [CSC_100X050X040_2]  232.33 36.27 180 bottom
C16  470pF_50V_2_DY  [CSC_100X050X040_2]  299.79 163.6 90 bottom
C17  1000PF_50V_2  [CSC_100X050X055_2]  231.52 57.48 90 top
C18  22pF_50V_2  [CSC_100X050X040_2]  21.13 64.19 0 top
C19  470pF_50V_2_DY  [CSC_100X050X040_2]  299.34 156.52 90 bottom
C20  22UF_6.3V_5_DY  [CSC_200X125X140_2]  262.68 31.91 90 bottom
C23  CSC0402_DY  [CSC_100X050X040_2]  298.45 154.79 270 bottom
C24  CSC0402_DY  [CSC_100X050X040_2]  299.79 165.38 90 bottom
C25  CSC0402_DY  [CSC_100X050X040_2]  298.83 167.03 90 bottom
C33  0.1uF_16V_2  [CSC_100X050X040_2]  270.81 56.14 270 top
C34  0.1uF_16V_2  [CSC_100X050X040_2]  124.06 74.83 270 top
C35  330uF_2.5V  [CSTJB_350X280X200_2_300]  153.08 74.04 90 bottom
C36  1uF_6.3V_2  [CSC_100X050X055_2]  119.45 74.83 90 top
C37  10uF_6.3V_3  [CSC_160X080X095_2]  115.59 85.63 90 bottom
C50  1000PF_50V_2  [CSC_100X050X055_2]  260.26 96.28 180 top
C51  0.1uF_16V_2  [CSC_100X050X040_2]  260.19 94.45 0 top
C62  0.1uF_16V_2  [CSC_100X050X040_2]  218.92 29.65 90 bottom
C63  0.1uF_16V_2  [CSC_100X050X040_2]  194.84 27.51 180 bottom
C65  CSC0402_DY  [CSC_100X050X040_2]  197.35 41.51 90 bottom
C68  1000PF_50V_2  [CSC_100X050X055_2]  16.74 33.89 180 top
C87  220pF_50V_2  [CSC_100X050X040_2]  301.39 23.73 0 bottom
C88  220pF_50V_2  [CSC_100X050X040_2]  301.39 22.84 0 bottom
C100  22uF_6.3V_3  [CLOONEY-6010B0219002-001]  225.83 52.73 270 top
C131  220pF_50V_2  [CSC_100X050X040_2]  278.96 58.9 270 bottom
C137  10uF_6.3V_3  [RANGERS-6010B0044902-001]  278.66 57.48 0 bottom
C138  0.01uF_50V_2  [CSC_100X050X040_2]  210.84 21.87 0 top
C139  0.1uF_16V_2  [CSC_100X050X040_2]  188.59 28.86 0 bottom
C140  0.1uF_16V_2  [CSC_100X050X040_2]  270.96 47.7 0 top
C250  2.2uF_6.3V_2  [CSC_100X050X040_2]  151.81 33.86 90 bottom
C251  100pF_50V_2  [CSC_100X050X040_2]  106.14 35.54 90 bottom
C252  0.1uF_16V_2  [CSC_100X050X040_2]  145.11 34.06 180 bottom
C253  1000PF_50V_2  [CSC_100X050X055_2]  195.98 162.33 90 top
C254  0.1uF_16V_2  [CSC_100X050X040_2]  191.84 162.41 270 top
C255  CSC0402_DY  [CSC_100X050X040_2]  153.01 33.86 270 bottom
C300  0.1uF_16V_2_DY  [CSC_100X050X040_2]  216.99 27.38 0 bottom
C301  0.1uF_16V_2_DY  [CSC_100X050X040_2]  218.79 32.16 90 bottom
C302  0.1uF_16V_2  [CSC_100X050X040_2]  193.37 41.89 0 bottom
C303  0.1uF_16V_2  [CSC_100X050X040_2]  211.07 22.23 90 bottom
C304  0.1uF_16V_2  [CSC_100X050X040_2]  211.96 22.23 270 bottom
C306  0.1uF_16V_2  [CSC_100X050X040_2]  201.93 23.5 180 bottom
C307  0.1uF_16V_2  [CSC_100X050X040_2]  196.97 33.73 270 bottom
C308  0.1uF_16V_2  [CSC_100X050X040_2]  213.36 44.22 90 bottom
C309  0.1uF_16V_2  [CSC_100X050X040_2]  222.45 20.65 270 top
C310  0.1uF_16V_2  [CSC_100X050X040_2]  203.78 44.22 90 bottom
C311  220pF_50V_2_DY  [CSC_100X050X040_2]  216.48 44.22 90 bottom
C312  220pF_50V_2_DY  [CSC_100X050X040_2]  217.37 44.22 90 bottom
C313  0.1uF_16V_2  [CSC_100X050X040_2]  217.67 36.38 0 bottom
C314  47pF_50V_2_DY  [CSC_100X050X040_2]  217.65 30.03 0 bottom
C315  12pF_50V_2_DY  [CSC_100X050X040_2]  209.29 22.23 270 bottom
C316  0.1uF_16V_2  [CSC_100X050X040_2]  216.05 24.62 180 bottom
C321  100pF_50V_2  [CSC_100X050X040_2]  198.24 41.51 270 bottom
C351  CSC0402_DY  [CSC_100X050X040_2]  200.17 43.92 270 bottom
C400  0.1uF_16V_2  [CSC_100X050X040_2]  278.11 101.85 180 top
C401  0.1uF_16V_2  [CSC_100X050X040_2]  287.28 98.89 180 bottom
C402  0.1uF_16V_2  [CSC_100X050X040_2]  278.11 100.9 180 top
C404  0.1uF_16V_2  [CSC_100X050X040_2]  277.85 104.52 180 top
C406  0.1uF_16V_2  [CSC_100X050X040_2]  281.48 105.31 270 top
C407  0.1uF_16V_2  [CSC_100X050X040_2]  286.31 104.9 0 top
C408  0.1uF_16V_2  [CSC_100X050X040_2]  288.79 102.99 270 top
C409  1uF_16V_2_DY  [CSC_100X050X055_2]  277.85 103.64 180 top
C410  4.7UF_6.3V_2_DY  [CSC_100X050X065_2]  278.1 102.75 180 top
C411  0.1uF_16V_2  [CSC_100X050X040_2]  278.63 95.56 180 top
C412  1uF_6.3V_2  [CSC_100X050X055_2]  279.65 99.53 90 top
C413  1000PF_50V_2_DY  [CSC_100X050X055_2]  282.09 94.24 0 top
C414  0.1uF_16V_2  [CSC_100X050X040_2]  282.09 93.35 0 top
C415  1uF_6.3V_2  [CSC_100X050X055_2]  282.09 95.13 0 top
C416  0.1uF_16V_2  [CSC_100X050X040_2]  289.48 94.94 270 top
C417  1uF_6.3V_2  [CSC_100X050X055_2]  288.59 94.94 270 top
C418  0.1uF_16V_2  [CSC_100X050X040_2]  282.09 92.46 0 top
C419  1uF_6.3V_2  [CSC_100X050X055_2]  288.77 100.87 0 top
C420  0.1uF_16V_2  [CSC_100X050X040_2]  285.48 93.72 0 top
C421  0.1uF_16V_2_DY  [CSC_100X050X040_2]  276.46 97.39 90 top
C422  10pF_50V_2  [CSC_100X050X040_2]  288.92 92.86 180 top
C423  10pF_50V_2  [CSC_100X050X040_2]  287.27 92.86 0 top
C424  1uF_6.3V_2  [CSC_100X050X055_2]  285.48 94.61 0 top
C425  0.1uF_16V_2  [CSC_100X050X040_2]  286.58 100.13 180 bottom
C426  0.1uF_16V_2  [CSC_100X050X040_2]  274.47 96.13 180 top
C427  10uF_6.3V_3  [REBORN-6010B0044901-003]  280.39 90.3 270 top
C428  10uF_6.3V_3  [REBORN-6010B0044901-003]  279.27 90.3 270 top
C429  1000pF_2000V_6  [CSC_320X160X130_2]  298.52 95.18 180 bottom
C433  0.01uF_50V_2  [CSC_100X050X040_2]  287.28 98 180 bottom
C436  10uF_6.3V_3  [REBORN-6010B0044901-003]  278.61 94.54 0 top
C437  0.1uF_16V_2  [CSC_100X050X040_2]  278.76 99.53 270 top
C438  1000PF_50V_2_DY  [CSC_100X050X055_2]  277.87 99.53 270 top
C478  10pF_50V_2  [CSC_100X050X040_2]  298.9 92.87 0 bottom
C479  10pF_50V_2_DY  [CSC_100X050X040_2]  298.9 93.75 0 bottom
C501  10uF_6.3V_3  [CSC_160X080X080_2]  15.57 50.88 180 top
C502  2.2UF_6.3V_2  [CSC_100X050X055_2]  17.6 50.7 90 top
C503  1uF_6.3V_2  [CSC_100X050X040_2]  21.18 50.78 90 top
C504  4.7uF_10V_3  [CSC_160X080X080_2]  13.03 51.41 270 top
C505  0.1uF_16V_2  [CSC_100X050X040_2]  14.09 52.3 270 top
C506  CSC0402_DY  [CSC_100X050X040_2]  13.15 62.54 0 top
C507  0.1uF_16V_2  [CSC_100X050X040_2]  14.78 59.95 180 top
C508  10uF_6.3V_3  [CSC_160X080X080_2]  15.52 63.1 0 top
C509  0.1uF_16V_2  [CSC_100X050X040_2]  14.78 61.73 180 top
C510  22pF_50V_2  [CSC_100X050X040_2]  19.68 62.11 180 top
C511  1uF_6.3V_2  [CSC_100X050X040_2]  22.07 50.78 90 top
C512  10uF_6.3V_3  [CSC_160X080X080_2]  24.46 51.31 90 top
C513  10uF_6.3V_3  [CSC_160X080X080_2]  25.68 51.31 270 top
C514  0.1uF_16V_2  [CSC_100X050X040_2]  24.69 55.07 270 top
C515  10uF_6.3V_3  [CSC_160X080X080_2]  25.75 54.72 270 top
C516  0.1uF_16V_2  [CSC_100X050X040_2]  21.87 62.49 90 top
C517  10uF_6.3V_3  [CSC_160X080X080_2]  22.93 63.02 90 top
C519  0.1uF_16V_2_DY  [CSC_100X050X040_2]  30.92 55.32 90 top
C520  0.1uF_16V_2  [CSC_100X050X040_2]  24.36 61.42 90 top
C521  10uF_6.3V_3  [CSC_160X080X080_2]  26.26 61.04 0 top
C522  10uF_6.3V_3_DY  [CSC_160X080X080_2]  28.14 55.02 90 top
C523  0.1uF_16V_2  [CSC_100X050X040_2]  12.01 46.54 270 top
C524  0.1uF_16V_2  [CSC_100X050X040_2]  26.26 47.32 0 top
C525  0.1uF_16V_2  [CSC_100X050X040_2]  12.01 59.52 90 top
C530  10uF_6.3V_3  [CSC_160X080X080_2]  18.23 62.77 90 top
C531  4.7uF_6.3V_3  [CSC_160X080X080_2]  13.15 55.93 180 top
C532  10uF_6.3V_3  [CSC_160X080X080_2]  23.21 51.31 270 top
C602  4.7uF_6.3V_3  [CSC_160X080X080_2]  15.41 49.66 0 top
C603  4.7uF_6.3V_3  [CSC_160X080X080_2]  15.41 48.44 0 top
C606  CSC0402_DY  [CSC_100X050X040_2]  293.61 121.32 180 bottom
C607  CSC0402_DY  [CSC_100X050X040_2]  298.4 121.47 180 bottom
C608  1000PF_50V_2  [CSC_100X050X055_2]  299.06 120.58 0 bottom
C609  1000PF_50V_2  [CSC_100X050X055_2]  296.78 120.71 180 bottom
C610  1000PF_50V_2  [CSC_100X050X055_2]  294.78 120.43 0 bottom
C611  1000PF_50V_2  [CSC_100X050X055_2]  292.87 120.3 180 bottom
C612  CSC0402_DY  [CSC_100X050X040_2]  279.63 121.85 180 bottom
C613  CSC0402_DY  [CSC_100X050X040_2]  274.98 121.24 90 bottom
C614  CSC0402_DY  [CSC_100X050X040_2]  299.23 151.16 180 bottom
C700  CSC0402_DY  [CSC_100X050X040_2]  137.64 30.51 0 bottom
C701  2.2uF_6.3V_2  [CSC_100X050X040_2]  134.82 38.15 180 bottom
C706  1uF_6.3V_2  [CSC_100X050X055_2]  140.36 41.84 0 bottom
C1300  1uF_6.3V_2  [CSC_100X050X055_2]  265.05 20.53 0 top
C1301  220pF_50V_2  [CSC_100X050X040_2]  268.96 21.9 0 top
C1310  10uF_6.3V_3  [CSC_160X080X080_2]  272.13 29.21 90 top
C1312  10uF_6.3V_3  [CSC_160X080X080_2]  293.04 28.68 0 top
C1313  0.1uF_16V_2  [CSC_100X050X040_2]  292.68 26.72 0 top
C1314  0.01uF_50V_2  [CSC_100X050X040_2]  292.68 27.61 0 top
C1315  12pF_50V_2  [CSC_100X050X040_2]  269.47 25.51 0 top
C1316  18pF_50V_2_DY  [CSC_100X050X040_2]  268.17 29.87 90 top
C1317  0.1uF_16V_2  [CSC_100X050X040_2]  268.96 23.19 0 top
C1318  0.1uF_16V_2  [CSC_100X050X040_2]  269.47 26.39 0 top
C1319  0.01uF_50V_2  [CSC_100X050X040_2]  269.74 29.9 90 top
C1322  0.1uF_16V_2  [CSC_100X050X040_2]  279.85 23.32 270 top
C1323  0.1uF_16V_2  [CSC_100X050X040_2]  278.96 23.32 270 top
C1700  22UF_6.3V_5  [CSC_200X125X140_2]  264.87 31.91 90 bottom
C1701  0.1uF_16V_2  [CSC_100X050X040_2]  266.29 28.07 270 bottom
C1702  0.01uF_50V_2  [CSC_100X050X040_2]  260.81 32.39 270 bottom
C1703  0.01uF_50V_2  [CSC_100X050X040_2]  259.92 32.39 270 bottom
C1704  0.1uF_16V_2  [CSC_100X050X040_2]  96.92 44.3 90 bottom
C1705  0.1uF_16V_2  [CSC_100X050X040_2]  96.03 44.3 90 bottom
C1706  0.1uF_16V_2  [CSC_100X050X040_2]  96.82 36.6 90 bottom
C1710  0.1uF_16V_2  [CSC_100X050X040_2]  97.71 36.6 90 bottom
C1711  10uF_6.3V_3  [CSC_160X080X080_2]  102.89 43.31 90 bottom
C1712  0.1uF_16V_2  [CSC_100X050X040_2]  101.75 42.68 90 bottom
C1713  0.1uF_16V_2  [CSC_100X050X040_2]  101.44 36.86 270 bottom
C1714  0.1uF_16V_2  [CSC_100X050X040_2]  95.91 36.6 270 bottom
C1715  0.1uF_16V_2  [CSC_100X050X040_2]  95.15 44.3 90 bottom
C1900  1000PF_50V_2  [CSC_100X050X055_2]  179.75 41.24 90 bottom
C1901  0.1uF_16V_2  [CSC_100X050X040_2]  177.87 41.25 90 bottom
C1902  10uF_6.3V_2  [CSC_100X050X070_2]  178.76 41.25 90 bottom
C1908  10uF_6.3V_2  [CSC_100X050X070_2]  180.39 21.68 270 bottom
C1909  0.22uF_6.3V_2  [CSC_100X050X040_2]  181.38 27.59 270 bottom
C1913  0.1uF_16V_2  [CSC_100X050X040_2]  65.66 54.33 90 bottom
C1916  0.22uF_6.3V_2  [CSC_100X050X040_2]  75.41 49.2 180 top
C1917  0.22uF_6.3V_2  [CSC_100X050X040_2]  87.98 41.56 180 bottom
C1918  0.22uF_6.3V_2  [CSC_100X050X040_2]  87.98 42.45 180 bottom
C1919  0.22uF_6.3V_2  [CSC_100X050X040_2]  75.41 48.31 180 top
C1920  0.22uF_6.3V_2  [CSC_100X050X040_2]  88.9 43.69 180 bottom
C1921  0.22uF_6.3V_2  [CSC_100X050X040_2]  88.9 44.58 180 bottom
C1922  0.22uF_6.3V_2  [CSC_100X050X040_2]  88.87 46.31 180 bottom
C1923  0.22uF_6.3V_2  [CSC_100X050X040_2]  88.87 47.2 180 bottom
C1924  0.22uF_6.3V_2  [CSC_100X050X040_2]  182.34 40.69 90 bottom
C1925  0.22uF_6.3V_2  [CSC_100X050X040_2]  183.23 40.69 90 bottom
C1926  0.22uF_6.3V_2  [CSC_100X050X040_2]  179.6 27.59 270 bottom
C1927  0.22uF_6.3V_2  [CSC_100X050X040_2]  178.71 27.59 270 bottom
C1928  0.22uF_6.3V_2  [CSC_100X050X040_2]  180.49 27.59 270 bottom
C1929  0.22uF_6.3V_2  [CSC_100X050X040_2]  183.16 27.59 270 bottom
C1930  0.22uF_6.3V_2  [CSC_100X050X040_2]  182.27 27.59 270 bottom
C1931  10uF_6.3V_2  [CSC_100X050X070_2]  66.82 33.94 270 bottom
C1932  0.1uF_16V_2  [CSC_100X050X040_2]  65.91 33.94 270 bottom
C1933  1000PF_50V_2  [CSC_100X050X055_2]  65.02 33.94 270 bottom
C1936  10uF_6.3V_2  [CSC_100X050X070_2]  66.54 54.33 90 bottom
C1937  0.1uF_16V_2  [CSC_100X050X040_2]  179.3 21.67 270 bottom
C2400  100uF_6.3V  [CSTJB2_362X305X190_2]  296.92 114.74 180 bottom
C2401  22uF_6.3V_5  [CSC_200X125X130_2]  300.25 115.95 270 bottom
C2402  0.1uF_16V_2  [CSC_100X050X040_2]  295.17 22.13 90 bottom
C2403  10uF_6.3V_3  [CSC_160X080X080_2]  294.1 21.92 90 bottom
C2404  0.1uF_16V_2  [CSC_100X050X040_2]  300.61 122.23 270 top
C2405  0.1uF_16V_2  [CSC_100X050X040_2]  285.71 120.7 90 bottom
C2406  0.1uF_16V_2  [CSC_100X050X040_2]  286.6 120.7 90 bottom
C2407  1uF_6.3V_2  [CSC_100X050X040_2]  289.91 120.91 90 bottom
C2408  0.1uF_16V_2  [CSC_100X050X040_2]  281.02 114.33 180 bottom
C2409  0.1uF_16V_2  [CSC_100X050X040_2]  287.52 119.94 90 bottom
C2410  0.1uF_6.3V_1  [CSC_060X030X030_2]  281.52 111.5 0 bottom
C2411  0.1uF_6.3V_1  [CSC_060X030X030_2]  281.52 112.11 0 bottom
C2412  0.1uF_6.3V_1  [CSC_060X030X030_2]  281.52 112.72 0 bottom
C2413  0.1uF_6.3V_1  [CSC_060X030X030_2]  281.52 113.33 0 bottom
C2414  22uF_6.3V_5  [CSC_200X125X130_2]  299.54 141.43 180 bottom
C2415  0.1uF_16V_2  [CSC_100X050X040_2]  300.17 140.16 180 bottom
C2416  100uF_6.3V  [CSTJB2_362X305X190_2]  299.34 144.76 90 bottom
C2417  0.1uF_16V_2  [CSC_100X050X040_2]  298.35 123.87 0 top
C2418  0.1uF_16V_2  [CSC_100X050X040_2]  298.35 124.76 0 top
C2419  0.1uF_16V_2  [CSC_100X050X040_2]  288.57 121.34 180 top
C2420  0.1uF_6.3V_1  [CSC_060X030X030_2]  289.08 124.46 0 top
C2421  0.1uF_6.3V_1  [CSC_060X030X030_2]  289.08 123.82 0 top
C2422  0.1uF_6.3V_1  [CSC_060X030X030_2]  289.08 123.06 0 top
C2423  0.1uF_6.3V_1  [CSC_060X030X030_2]  289.08 122.43 0 top
C2424  22uF_6.3V_5_DY  [CSC_200X125X130_2]  291.21 120.7 90 bottom
C2425  0.1uF_16V_2  [CSC_100X050X040_2]  296.85 126.5 0 top
C2500  0.33UF_25V_2  [CSC_100X050X055_2]  304.77 24.26 90 top
C2501  0.22UF_25V_2  [CSC_100X050X055_2]  301.98 24.24 90 top
C2502  0.22UF_25V_2  [CSC_100X050X055_2]  305.97 22.18 90 bottom
C2503  0.22UF_25V_2  [CSC_100X050X055_2]  306.85 22.18 90 bottom
C2504  0.22UF_25V_2  [CSC_100X050X055_2]  302.87 24.24 90 top
C2505  0.1uF_16V_2  [CSC_100X050X040_2]  281.28 33.71 90 top
C2506  4.7UF_6.3V_2  [CSC_100X050X065_2]  282.17 33.71 90 top
C2507  10uF_6.3V_3_DY  [CSC_160X080X080_2]  289.23 33.33 90 top
C2508  0.1uF_16V_2  [CSC_100X050X040_2]  288.16 33.71 90 top
C2509  0.33UF_25V_2  [CSC_100X050X055_2]  303.4 24.11 90 bottom
C2510  0.33UF_25V_2  [CSC_100X050X055_2]  304.29 24.11 90 bottom
C2511  0.33UF_25V_2  [CSC_100X050X055_2]  305.66 24.26 90 top
C2518  0.1uF_16V_2  [CSC_100X050X040_2]  297.56 29.37 180 top
C2519  0.1uF_16V_2  [CSC_100X050X040_2]  297.56 28.48 180 top
C2520  100uF_6.3V  [CSTJB2_362X305X190_2]  300.99 30.18 180 bottom
C2521  0.1uF_16V_2  [CSC_100X050X040_2]  302.46 27.99 180 bottom
C2522  22uF_6.3V_5  [CSC_200X125X130_2]  297.99 21.77 180 top
C2547  10UF_25V_5  [CSC_200X125X140_2]  306.6 6.61 180 top
C2548  10UF_25V_5  [CSC_200X125X140_2]  309.52 8.46 0 top
C2549  1uF_6.3V_2  [CSC_100X050X055_2]  304.29 8.11 270 top
C2551  10UF_25V_5  [CSC_200X125X140_2]  306.6 8.28 180 top
C2552  100uF_6.3V_DY  [CSTJB2_362X305X190_2]  307.29 10.27 180 bottom
C2990  10uF_6.3V_3  [RANGERS-6010B0044902-001]  231.95 55.65 0 top
C3000  2.2UF_6.3V_2  [CSC_100X050X055_2]  21.26 81.64 0 bottom
C3001  0.1uF_16V_2  [CSC_100X050X040_2]  19.17 76.33 180 bottom
C3002  2.2UF_6.3V_2  [CSC_100X050X055_2]  19.17 75.44 180 bottom
C3003  CSC0402_DY  [CSC_100X050X040_2]  17.93 76.46 270 bottom
C3004  10pF_50V_2_DY  [CSC_100X050X040_2]  28.57 61.32 270 top
C3005  10pF_50V_2_DY  [CSC_100X050X040_2]  29.94 61.29 270 top
C3007  CSC0402_DY  [CSC_100X050X040_2]  38.27 60.35 180 bottom
C3008  680pF_50V_2_DY  [CSC_100X050X040_2]  36.56 61.57 180 bottom
C3009  0.1uF_25V_2  [CSC_100X050X040_2]  25.75 65.26 270 top
C3010  4.7uF_25V_3  [CSC_160X080X095_2]  24.69 64.9 270 top
C3011  CSC0402_DY  [CSC_100X050X040_2]  29.69 63.4 0 bottom
C3012  CSC0402_DY  [CSC_100X050X040_2]  27.68 63.63 270 top
C3013  0.1uF_6.3V_1  [CSC_060X030X030_2]  45.02 60.78 270 bottom
C3014  0.1uF_6.3V_1  [CSC_060X030X030_2]  44.41 60.78 270 bottom
C3016  0.1uF_6.3V_1  [CSC_060X030X030_2]  46.05 61.19 270 bottom
C3017  0.1uF_6.3V_1  [CSC_060X030X030_2]  46.66 61.19 270 bottom
C3019  0.1uF_6.3V_1  [CSC_060X030X030_2]  42.69 60.78 270 bottom
C3020  0.1uF_6.3V_1  [CSC_060X030X030_2]  43.3 60.78 270 bottom
C3026  0.1uF_6.3V_1  [CSC_060X030X030_2]  48.23 61.19 270 bottom
C3027  0.1uF_6.3V_1  [CSC_060X030X030_2]  47.62 61.19 270 bottom
C3028  0.1uF_6.3V_1  [CSC_060X030X030_2]  50.19 61.8 270 bottom
C3029  0.1uF_6.3V_1  [CSC_060X030X030_2]  49.55 61.8 270 bottom
C3500  4.7UF_6.3V_2  [CSC_100X050X065_2]  229.61 20.6 90 bottom
C3501  4.7UF_6.3V_2  [CSC_100X050X065_2]  237.49 21.26 0 bottom
C3502  0.1uF_16V_2  [CSC_100X050X040_2]  237.49 20.37 0 bottom
C3503  0.1uF_16V_2  [CSC_100X050X040_2]  228.72 20.6 90 bottom
C3504  0.1uF_16V_2  [CSC_100X050X040_2]  234.59 28.53 90 bottom
C3505  0.1uF_16V_2  [CSC_100X050X040_2]  233.7 28.53 90 bottom
C4100  10uF_6.3V_3  [CSC_160X080X095_2]  141.8 88.12 90 bottom
C4101  1uF_6.3V_2  [CSC_100X050X055_2]  155.14 62.23 0 top
C4102  1uF_6.3V_2  [CSC_100X050X055_2]  155.14 63.15 0 top
C4103  1uF_6.3V_2  [CSC_100X050X055_2]  155.14 64.06 0 top
C4104  0.1uF_16V_2  [CSC_100X050X040_2]  144.29 84.81 180 bottom
C4105  2.2UF_6.3V_2  [CSC_100X050X055_2]  144.29 85.7 180 bottom
C4106  10uF_6.3V_3  [CSC_160X080X095_2]  107.29 85.09 180 bottom
C4107  10uF_6.3V_3  [CSC_160X080X095_2]  107.03 73.99 180 top
C4108  10uF_6.3V_3  [CSC_160X080X095_2]  122.98 85.73 90 bottom
C4109  10uF_6.3V_3  [CSC_160X080X095_2]  112.54 85.6 90 bottom
C4111  2.2UF_6.3V_2  [CSC_100X050X055_2]  123.16 74.83 270 top
C4113  10uF_6.3V_3  [CSC_160X080X095_2]  121 74.65 90 top
C4114  10uF_6.3V_3  [CSC_160X080X095_2]  114.83 74.7 90 top
C4115  10uF_6.3V_3  [CSC_160X080X095_2]  107.03 75.24 180 top
C4116  1uF_6.3V_2  [CSC_100X050X055_2]  109.62 85.3 90 bottom
C4117  1uF_6.3V_2  [CSC_100X050X055_2]  120.11 85.5 90 bottom
C4118  1uF_6.3V_2  [CSC_100X050X055_2]  119.2 85.5 90 bottom
C4119  1uF_6.3V_2  [CSC_100X050X055_2]  110.79 85.3 90 bottom
C4120  1uF_6.3V_2  [CSC_100X050X055_2]  109.95 74.81 90 top
C4121  1uF_6.3V_2  [CSC_100X050X055_2]  111.55 74.86 270 top
C4123  1uF_6.3V_2  [CSC_100X050X055_2]  115.9 74.83 90 top
C4125  1uF_6.3V_2  [CSC_100X050X055_2]  144.73 72.16 180 top
C4126  1uF_6.3V_2  [CSC_100X050X055_2]  144.73 73.08 180 top
C4127  1uF_6.3V_2  [CSC_100X050X055_2]  144.73 73.99 180 top
C4128  10uF_6.3V_3  [CSC_160X080X095_2]  144.98 75.06 180 top
C4129  0.1uF_16V_2  [CSC_100X050X040_2]  151.41 67.47 180 top
C4130  2.2UF_6.3V_2  [CSC_100X050X055_2]  151.41 68.35 180 top
C4131  1uF_6.3V_2  [CSC_100X050X055_2]  144.12 88.47 90 bottom
C4132  1uF_6.3V_2  [CSC_100X050X055_2]  156.64 71.68 0 bottom
C4133  1uF_6.3V_2  [CSC_100X050X055_2]  156.64 72.57 0 bottom
C4134  1uF_6.3V_2  [CSC_100X050X055_2]  145.03 88.47 90 bottom
C4135  10uF_6.3V_3  [CSC_160X080X095_2]  156.99 69.29 0 bottom
C4136  10uF_6.3V_3  [CSC_160X080X095_2]  156.99 70.54 0 bottom
C4137  10uF_6.3V_3  [CSC_160X080X095_2]  143.05 88.12 90 bottom
C4138  10uF_6.3V_3  [CSC_160X080X095_2]  155.34 65.15 0 top
C4139  330uF_2.5V  [CSTJB_350X280X200_2_300]  79.36 70.44 270 bottom
C4140  10uF_6.3V_3  [CSC_160X080X095_2]  115.41 70.69 0 top
C4141  1uF_6.3V_2  [CSC_100X050X055_2]  125.85 61.7 270 top
C4142  10uF_6.3V_3  [CSC_160X080X095_2]  125.37 71.56 90 top
C4143  10uF_6.3V_3  [CSC_160X080X095_2]  126.62 71.56 90 top
C4144  0.1uF_16V_2  [CSC_100X050X040_2]  128.72 62.06 0 top
C4145  2.2UF_6.3V_2  [CSC_100X050X055_2]  128.72 61.17 0 top
